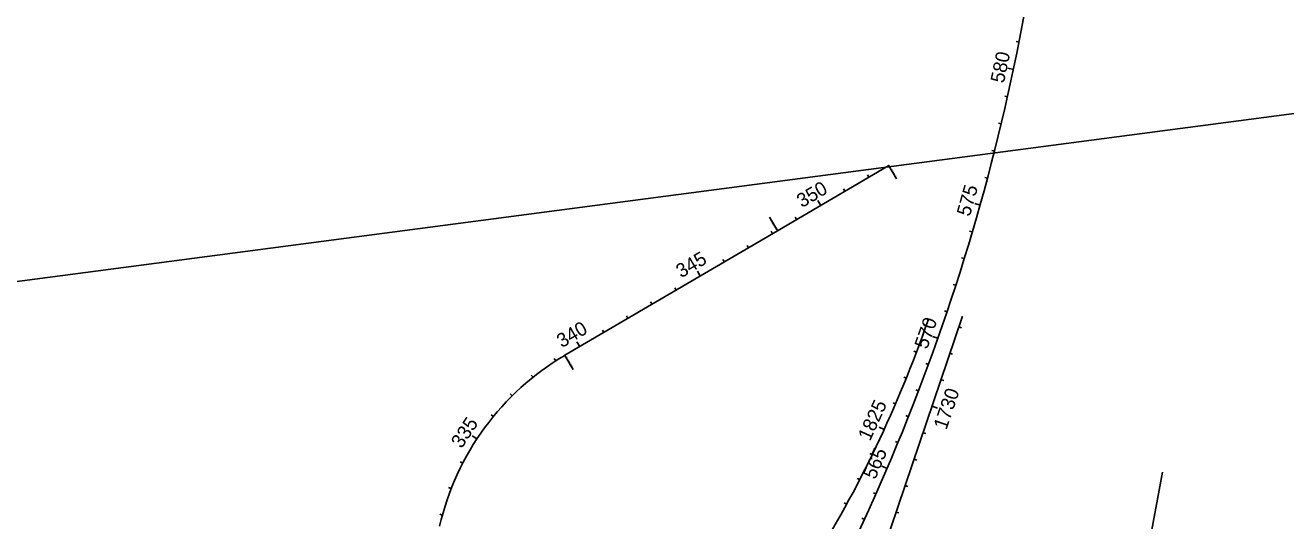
# Model space of a CAD drawing. Extents: x 448091 to 665917, y 1461380 to 1587607.
# Drawn here: x 483504 to 488016, y 1572013 to 1573786 of the extents above; entities that cross this region are included whole.
import ezdxf

# ---------------------------------------------------------------- set-up
doc = ezdxf.new("R2010")
doc.units = 0
for name, color, linetype in [('AttenuatorTM', 7, 'Continuous'), ('BarrierWall_ep', 7, 'Continuous'), ('BLSurveyCntrl_ep', 7, 'Continuous'), ('BLSurveyField_ep', 7, 'Continuous'), ('BLSurveySymbl_ep', 7, 'Continuous'), ('TextShtNo', 7, 'Continuous'), ('TextTitle', 7, 'Continuous')]:
    doc.layers.add(name, color=color, linetype=linetype)

msp = doc.modelspace()

# ---------------------------------------------------------------- linework, layer by layer
at = {"layer": 'AttenuatorTM'}
for p, q in [((486595.5, 1573283.1), (486622.7, 1573236.6)), ((486196.7, 1573051.9), (486168.6, 1573099.8)), ((485436, 1572604.1), (485465.1, 1572554.5))]:
    msp.add_line(p, q, dxfattribs=at)
for centre in [(486595, 1573284), (486197.2, 1573051), (486858.1, 1572742.1), (486736, 1572731.2), (485435.5, 1572605)]:
    msp.add_circle(centre, 1, dxfattribs=at)
at = {"layer": 'BarrierWall_ep'}
for p, q in [((480007.6, 1572413.4), (490159.9, 1573748.2)), ((487575.5, 1572187.2), (487258.3, 1570499.8))]:
    msp.add_line(p, q, dxfattribs=at)
at = {"layer": 'BLSurveyCntrl_ep'}
for p, q in [((486197.2, 1573051), (486595, 1573284)), ((485435.5, 1572605), (486197.2, 1573051)), ((486545.4, 1571818.2), (486858.1, 1572742.1))]:
    msp.add_line(p, q, dxfattribs=at)
for centre, radius, start, end in [((482672.1, 1574136.5), 4300, 327.8735, 340.9248), ((485918.1, 1571780.9), 954.9, 120.3536, 167.1061)]:
    msp.add_arc(centre, radius, start, end, dxfattribs=at)
at = {"layer": 'BLSurveyField_ep'}
for p, q in [((486524.1, 1573242.5), (486519.1, 1573251.1)), ((486437.8, 1573191.9), (486432.8, 1573200.6)), ((486351.5, 1573141.4), (486341.4, 1573158.7)), ((486265.3, 1573090.9), (486260.2, 1573099.5)), ((486179, 1573040.3), (486173.9, 1573049)), ((486092.7, 1572989.8), (486087.6, 1572998.4)), ((486006.4, 1572939.3), (486001.3, 1572947.9)), ((485920.1, 1572888.7), (485910, 1572906)), ((485833.8, 1572838.2), (485828.7, 1572846.8)), ((485747.5, 1572787.7), (485742.4, 1572796.3)), ((485661.2, 1572737.1), (485656.2, 1572745.8)), ((485574.9, 1572686.6), (485569.9, 1572695.2)), ((486728.8, 1572710.5), (486719.4, 1572713.8)), ((486846.2, 1572707), (486855.7, 1572703.8)), ((485488.6, 1572636.1), (485478.5, 1572653.3)), ((486694.5, 1572616.6), (486685.2, 1572620.1)), ((486814.2, 1572612.3), (486823.6, 1572609.1)), ((485402.7, 1572584.9), (485397.3, 1572593.3)), ((485321.5, 1572526.6), (485315.3, 1572534.4)), ((486658.1, 1572523.4), (486648.8, 1572527.2)), ((486782.1, 1572517.6), (486791.6, 1572514.4)), ((485246.8, 1572460.2), (485239.8, 1572467.3)), ((486619.5, 1572431.2), (486610.3, 1572435.2)), ((486750, 1572422.9), (486769, 1572416.5)), ((485179.5, 1572386.3), (485171.8, 1572392.6)), ((486578.8, 1572339.9), (486560.6, 1572348.2)), ((485120.3, 1572305.8), (485103.6, 1572316.8)), ((486718, 1572328.2), (486727.4, 1572325)), ((486536, 1572249.5), (486527, 1572253.9)), ((485069.8, 1572219.5), (485060.9, 1572224.1)), ((486685.9, 1572233.4), (486695.4, 1572230.2)), ((486491, 1572160.2), (486482.1, 1572164.8)), ((485028.6, 1572128.4), (485019.3, 1572132.1)), ((486653.8, 1572138.7), (486663.3, 1572135.5)), ((486444, 1572071.9), (486435.3, 1572076.7)), ((484997.2, 1572033.6), (484987.5, 1572036.2)), ((486621.8, 1572044), (486631.3, 1572040.8))]:
    msp.add_line(p, q, dxfattribs=at)
at = {"layer": 'TextShtNo'}
msp.add_arc((479567.5, 1575210.1), 7639.4, 330.62472, 354.97487, dxfattribs=at)
at = {"layer": 'TextTitle'}
for p, q in [((487061.4, 1573726.2), (487051.6, 1573728.1)), ((487041.4, 1573628.2), (487021.8, 1573632.3)), ((487020, 1573530.5), (487010.3, 1573532.8)), ((486997.4, 1573433.1), (486987.7, 1573435.4)), ((486973.5, 1573336), (486963.8, 1573338.5)), ((486948.3, 1573239.2), (486938.7, 1573241.8)), ((486921.9, 1573142.8), (486902.7, 1573148.2)), ((486894.2, 1573046.7), (486884.6, 1573049.5)), ((486865.3, 1572951), (486855.7, 1572953.9)), ((486835.1, 1572855.6), (486825.6, 1572858.7)), ((486803.6, 1572760.7), (486794.2, 1572763.9)), ((486770.9, 1572666.2), (486752.1, 1572672.9)), ((486737, 1572572.1), (486727.6, 1572575.6)), ((486701.9, 1572478.5), (486692.5, 1572482.1)), ((486665.5, 1572385.4), (486656.2, 1572389.1)), ((486627.9, 1572292.7), (486618.7, 1572296.5)), ((486589.1, 1572200.5), (486570.8, 1572208.4)), ((486549.2, 1572108.9), (486540, 1572112.9)), ((486508, 1572017.8), (486498.9, 1572021.9))]:
    msp.add_line(p, q, dxfattribs=at)

# ---------------------------------------------------------------- texts
at = {"layer": 'AttenuatorTM'}
for s, rotation, p in [('PC STA 352+82.11', 300.3536, (486600, 1573278.8)), ('POT STA 348+21.11', 120.3536, (486192.1, 1573056.2)), ('PT STA 339+38.45', 300.3536, (485440.6, 1572599.8))]:
    msp.add_text(s, height=3.5, rotation=rotation, dxfattribs=at).set_placement(p)
at = {"layer": 'BLSurveySymbl_ep'}
for s, rotation, p in [('350', 30.3536, (486284.1, 1573131.6)), ('345', 30.3536, (485851.9, 1572880.3)), ('340', 30.3536, (485424.7, 1572630.4)), ('1730', 71.2981, (486801.3, 1572335.9)), ('1825', 65.3025, (486527.8, 1572295.5)), ('335', 56.6605, (485066, 1572269))]:
    msp.add_text(s, height=50, rotation=rotation, dxfattribs=at).set_placement(p)
at = {"layer": 'TextTitle'}
for s, rotation, p in [('580', 78.0493, (487007.2, 1573576.7)), ('575', 74.2993, (486885.1, 1573099.5)), ('570', 70.5493, (486732.4, 1572624.4)), ('565', 66.7993, (486546.5, 1572157.9))]:
    msp.add_text(s, height=50, rotation=rotation, dxfattribs=at).set_placement(p)

doc.saveas('drawing.dxf')
